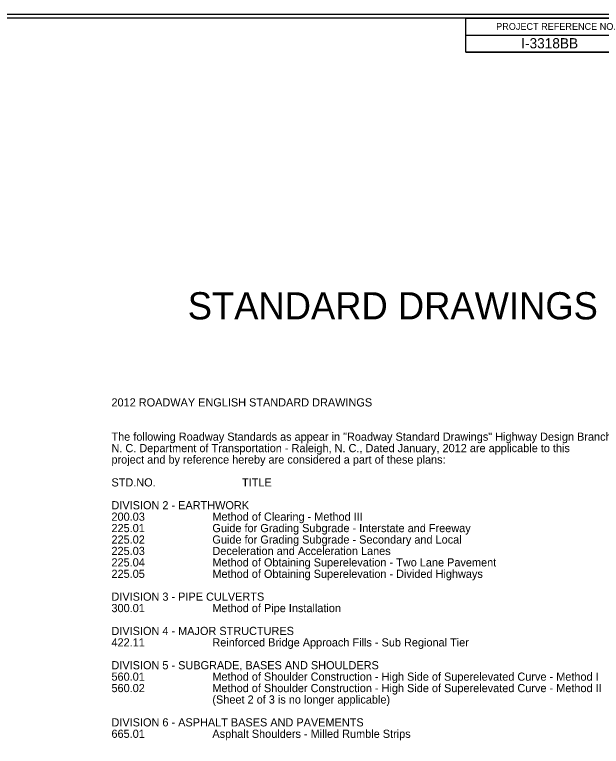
# Model space of a CAD drawing. Extents: x 2241278 to 2254132, y 649924 to 670434.
# Drawn here: x 2250231 to 2252389, y 652610 to 655299 of the extents above; entities that cross this region are included whole.
import ezdxf

# ---------------------------------------------------------------- set-up
doc = ezdxf.new("R2010")
doc.units = 0
for name, color, linetype in [('Sheet Data Field CELL', 7, 'Continuous'), ('Sheet Data Text CELL', 7, 'Continuous'), ('Sheet Plan CELL', 7, 'Continuous'), ('Sheet Plot Border Inside CELL', 7, 'Continuous')]:
    doc.layers.add(name, color=color, linetype=linetype)

msp = doc.modelspace()

# ---------------------------------------------------------------- linework, layer by layer
at = {"layer": 'Sheet Plan CELL'}
for p, q in [((2251891, 655223.9), (2252891.3, 655223.9)), ((2251891, 655161.4), (2252891.3, 655161.4)), ((2251891, 655161.4), (2252891.3, 655161.4))]:
    msp.add_line(p, q, dxfattribs=at)
for points in [[(2252891.3, 655286.7), (2245391.3, 655286.7), (2245391.3, 650036.7), (2252891.3, 650036.7)], [(2251891, 655286.7), (2252891.3, 655286.7), (2252891.3, 655161.4), (2251891, 655161.4)]]:
    msp.add_lwpolyline(points, close=True, dxfattribs=at)
at = {"layer": 'Sheet Plot Border Inside CELL'}
msp.add_lwpolyline([(2244623.8, 650024.2), (2252953.8, 650024.2), (2252953.8, 655299.2), (2244623.8, 655299.2)], close=True, dxfattribs=at)

# ---------------------------------------------------------------- texts
at = {"layer": 'Sheet Data Field CELL'}
msp.add_text('I-3318BB', height=37.5, dxfattribs=at).set_placement((2252094.1, 655175.2))
at = {"layer": 'Sheet Data Text CELL'}
for s, height, p in [('STANDARD DRAWINGS', 100, (2250867.8, 654179.1)), ('2012 ROADWAY ENGLISH STANDARD DRAWINGS', 30, (2250587.3, 653859.1)), ('The following Roadway Standards as appear in "Roadway Standard Drawings" Highway Design Branch -', 30, (2250587.3, 653733.1)), ('N. C. Department of Transportation - Raleigh, N. C., Dated January, 2012 are applicable to this ', 30, (2250587.3, 653691.1)), ('project and by reference hereby are considered a part of these plans:', 30, (2250587.3, 653649.1)), ('STD.NO.', 30, (2250587.3, 653565.1)), ('TITLE', 30, (2251067.3, 653565.1)), ('DIVISION 2 - EARTHWORK', 30, (2250587.3, 653481.1)), ('200.03', 30, (2250587.3, 653439.1)), (' Method of Clearing - Method III', 30, (2250947.3, 653439.1)), ('225.01', 30, (2250587.3, 653397.1)), (' Guide for Grading Subgrade - Interstate and Freeway', 30, (2250947.3, 653397.1)), ('225.02', 30, (2250587.3, 653355.1)), (' Guide for Grading Subgrade - Secondary and Local', 30, (2250947.3, 653355.1)), ('225.03', 30, (2250587.3, 653313.1)), (' Deceleration and Acceleration Lanes', 30, (2250947.3, 653313.1)), ('225.04', 30, (2250587.3, 653271.1)), (' Method of Obtaining Superelevation - Two Lane Pavement', 30, (2250947.3, 653271.1)), ('225.05', 30, (2250587.3, 653229.1)), (' Method of Obtaining Superelevation - Divided Highways', 30, (2250947.3, 653229.1)), ('DIVISION 3 - PIPE CULVERTS', 30, (2250587.3, 653145.1)), ('300.01', 30, (2250587.3, 653103.1)), (' Method of Pipe Installation ', 30, (2250947.3, 653103.1)), ('DIVISION 4 - MAJOR STRUCTURES', 30, (2250587.3, 653019.1)), ('422.11', 30, (2250587.3, 652977.1)), (' Reinforced Bridge Approach Fills - Sub Regional Tier', 30, (2250947.3, 652977.1)), ('DIVISION 5 - SUBGRADE, BASES AND SHOULDERS', 30, (2250587.3, 652893.1)), ('560.01', 30, (2250587.3, 652851.1)), (' Method of Shoulder Construction - High Side of Superelevated Curve - Method I', 30, (2250947.3, 652851.1)), ('560.02', 30, (2250587.3, 652809.1)), (' Method of Shoulder Construction - High Side of Superelevated Curve - Method II ', 30, (2250947.3, 652809.1)), (' (Sheet 2 of 3 is no longer applicable)', 30, (2250947.3, 652767.1)), ('DIVISION 6 - ASPHALT BASES AND PAVEMENTS', 30, (2250587.3, 652683.1)), ('665.01', 30, (2250587.3, 652641.1)), (' Asphalt Shoulders - Milled Rumble Strips', 30, (2250947.3, 652641.1))]:
    msp.add_text(s, height=height, dxfattribs=at).set_placement(p)
at = {"layer": 'Sheet Plan CELL'}
msp.add_text('PROJECT REFERENCE NO.', height=25, dxfattribs=at).set_placement((2252002, 655243.2))

doc.saveas('drawing.dxf')
